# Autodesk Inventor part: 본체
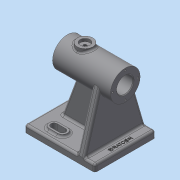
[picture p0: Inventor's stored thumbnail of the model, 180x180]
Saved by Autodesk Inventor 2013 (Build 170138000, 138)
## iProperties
Created: 2019-10
Part Number: 본체
Material: Generic
Document SubType Name: Modeling
Designer: Administrator
Density: 1 g/cm^3
Author: Administrator
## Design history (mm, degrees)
sketch "스케치1"
  geometry: L1 (-50, 43)-(50, 43); L2 (50, 43)-(50, -43); L3 (50, -43)-(-50, -43); L4 (-50, -43)-(-50, 43); 1 further point
  constraints: 8 end point, 2 parallel, 1 horizontal, 1 perpendicular
  dimensions: "d0" = 100 distance of L1.start L1.end; "d2" = 86 distance of L1.end L2.end; "d6" = 50 distance from line of L2 point (0, 0); "d7" = 43 distance from line of point (0, 0) L1
extrude "돌출1" new body sketch "스케치1" distance "d8" = 10; taper "d9" = 0 deg
sketch "스케치2"
  geometry: L1 (-50, 43)-(-50, -43) reference; L2 (50, -43)-(50, 43) reference; L3 (-24, 34)-(-12, 34); L4 (-12, 20)-(-24, 20); A1 r 7 centre (-12, 27) between (-12, 20) and (-12, 34); A2 r 7 centre (-24, 27) between (-24, 34) and (-24, 20); 1 further point
  constraints: 4 end point, 4 point on circle, 4 tangent, 2 centre point, 1 parallel, 1 perpendicular
  dimensions: "d10" = 12 distance of A1.centre A2.centre; "d12" = 14 distance between parallel lines of L4 L3; "d13" = 26 distance from line of L1 A2.centre; "d14" = 27 vertical distance of A2.centre point (0, 0)
extrude "돌출2" join sketch "스케치2" distance "d15" = 3; taper "d16" = 0 deg
sketch "스케치3"
  geometry: L1 (-24, 20)-(-12, 20) reference; L2 (-24, 31.5)-(-12, 31.5); L3 (-12, 22.5)-(-24, 22.5); A1 r 7 centre (-24, 27) between (-24, 34) and (-24, 20) reference; A2 r 7 centre (-12, 27) between (-12, 20) and (-12, 34) reference; A3 r 4.5 centre (-12, 27) between (-12, 22.5) and (-12, 31.5); A4 r 4.5 centre (-24, 27) between (-24, 31.5) and (-24, 22.5); 1 further point
  constraints: 4 end point, 4 point on circle, 4 tangent, 2 centre point, 2 coincident, 2 parallel
  dimensions: "d17" = 9 distance between parallel lines of L3 L2
extrude "돌출3" cut sketch "스케치3" distance "d19" = 13; taper "d20" = 0 deg
sketch "스케치5"
  geometry: L1 (50, 10)-(-50, 10) reference; L2 (-50, 86)-(32, 86); L3 (-50, 97.5)-(12, 97.5); L4 (-50, 97.5)-(-50, 107); L5 (-50, 107)-(32, 107); L6 (32, 107)-(32, 100.5); L7 (12, 97.5)-(12, 100.5); L8 (12, 100.5)-(32, 100.5); L9 (50, 0)-(-50, 0) reference; 1 further point
  constraints: 14 end point, 3 vertical alignment, 2 parallel, 1 horizontal, 1 perpendicular, 1 vertical
  dimensions: "d22" = 82 distance of L2.start L2.end; "d28" = 23 diameter of L3 L2; "d29" = 62 distance between parallel lines of L7 L4; "d30" = 29 diameter of L8 L2; "d31" = 42 diameter of L5 L2; "d72" = 86 distance between parallel lines of L9 L2
revolve "회전1" sketch "스케치5" stored, may be unused: angle "d32" = 90 deg
sketch "스케치6"
  geometry: C1 r 21 at (0, 0) reference; 5 further points
  constraints: 2 horizontal alignment, 2 vertical alignment
  dimensions: "d33" = 18 distance of C1.centre point (-18, 0); "d34" = 36 distance of point (18, 0) point (-18, 0); "d35" = 18 distance of point (0, 18) C1.centre; "d36" = 36 distance of point (0, -18) point (0, 18)
hole "구멍1" sketch "스케치6" at (-18, 0), (0, 18), (18, 0), (0, -18) diameter "d37" = 2.459; stored, may be unused: countersink angle "d41" = 90 deg, drill point angle "d43" = 118 deg; dims "d38" = 8, "d39" = 4, "d40" = 2, "d42" = 10
sketch "스케치7"
  geometry: C1 r 14.5 at (0, 0) reference; 5 further points
  constraints: 2 horizontal alignment, 2 vertical alignment
  dimensions: "d44" = 18 distance of C1.centre point (18, 0); "d45" = 36 distance of point (-18, 0) point (18, 0); "d46" = 18 distance of point (0, -18) C1.centre; "d47" = 36 distance of point (0, -18) point (0, 18)
hole "구멍2" sketch "스케치7" at (18, 0), (0, -18), (-18, 0), (0, 18) diameter "d48" = 2.459; stored, may be unused: countersink angle "d52" = 90 deg, drill point angle "d54" = 118 deg; dims "d49" = 8, "d50" = 4, "d51" = 2, "d53" = 10
node "작업 평면3"
sketch "스케치10"
  geometry: L1 (43, 10)-(-43, 10) reference; L2 (-43, 10)-(-21, 86); L3 (43, 10)-(21, 86); L4 (-43, 10)-(43, 10); A1 r 21 centre (0, 86) between (-21, 86) and (21, 86) reference; A2 r 21 centre (0, 86) between (-21, 86) and (21, 86); 1 further point
  constraints: 6 end point, 4 point on circle, 2 horizontal alignment, 1 centre point, 1 coincident, 1 collinear
extrude "돌출4" join sketch "스케치10" distance "d61" = 10; taper "d62" = 0 deg
sketch "스케치11"
  geometry: L1 (-50, 65)-(32, 65) reference; L2 (50, 10)-(-25, 10) reference; L3 (14.982, 65)-(35, 10); L4 (50, 0)-(50, 10) reference; 1 further point
  constraints: 2 end point, 2 point on line
  dimensions: "d63" = 15 distance from line of L3.end L4; "d64" = 70 deg angle of L2 L3
feature "리브1" sketch "스케치11" dims "d65" = 1, "d66" = 10, "d67" = 0, "d68" = 0, "d69" = 1, "d70" = 1
sketch "스케치12"
  geometry: C1 r 21 at (0, 86) reference; 1 further point
node "작업 평면5"
sketch "스케치13"
  geometry: L1 (-32, 21)-(-32, -21) reference; C1 r 11 at (-7, 0); 1 further point
  constraints: 1 centre point, 1 horizontal alignment
  dimensions: "d76" = 25 distance from line of L1 C1.centre; "d77" = 22 diameter of C1
extrude "돌출5" join sketch "스케치13" stored distance "d78" = 10; taper "d79" = 0 deg
sketch "스케치14"
  geometry: C1 r 11 at (0, 0) reference; C2 r 7 at (0, 0); 1 further point
  constraints: 1 centre point, 1 coincident
  dimensions: "d80" = 14 diameter of C2
extrude "돌출6" cut sketch "스케치14" distance "d82" = 4; taper "d83" = 0 deg
sketch "스케치15"
  geometry: 3 further points
  constraints: 1 coincident, 1 horizontal alignment
hole "구멍3" sketch "스케치15" at (0, 0) diameter "d84" = 4.917; stored, may be unused: countersink angle "d88" = 90 deg, drill point angle "d90" = 0 deg; dims "d85" = 8, "d86" = 4, "d87" = 2, "d89" = 24
sketch "스케치17"
  geometry: L1 (50, -43)-(50, 43) reference; L2 (35, -43)-(50, -43) reference; 2 further points
  constraints: 1 other
  dimensions: "d91" = 43 distance from line of L2 point (43, 0); "d92" = 7 distance from line of L1 point (43, 0)
feature "엠보싱1" sketch "스케치17" dims "d0" = 100, "d2" = 86, "d6" = 50, "d7" = 43, "d93" = 0.5, "d94" = 0
chamfer "모따기1" distance "d95" = 1; stored, may be unused: second distance "d96" = 2, angle "d97" = 45 deg
fillet "모깎기1" dims "d98" = 3
fillet "모깎기2" dims "d99" = 3
fillet "모깎기3" dims "d100" = 3
fillet "모깎기4" dims "d101" = 3
fillet "모깎기5" dims "d102" = 3
node "솔리드1"
mirror "대칭1"
other parameters: "d59" = 35
